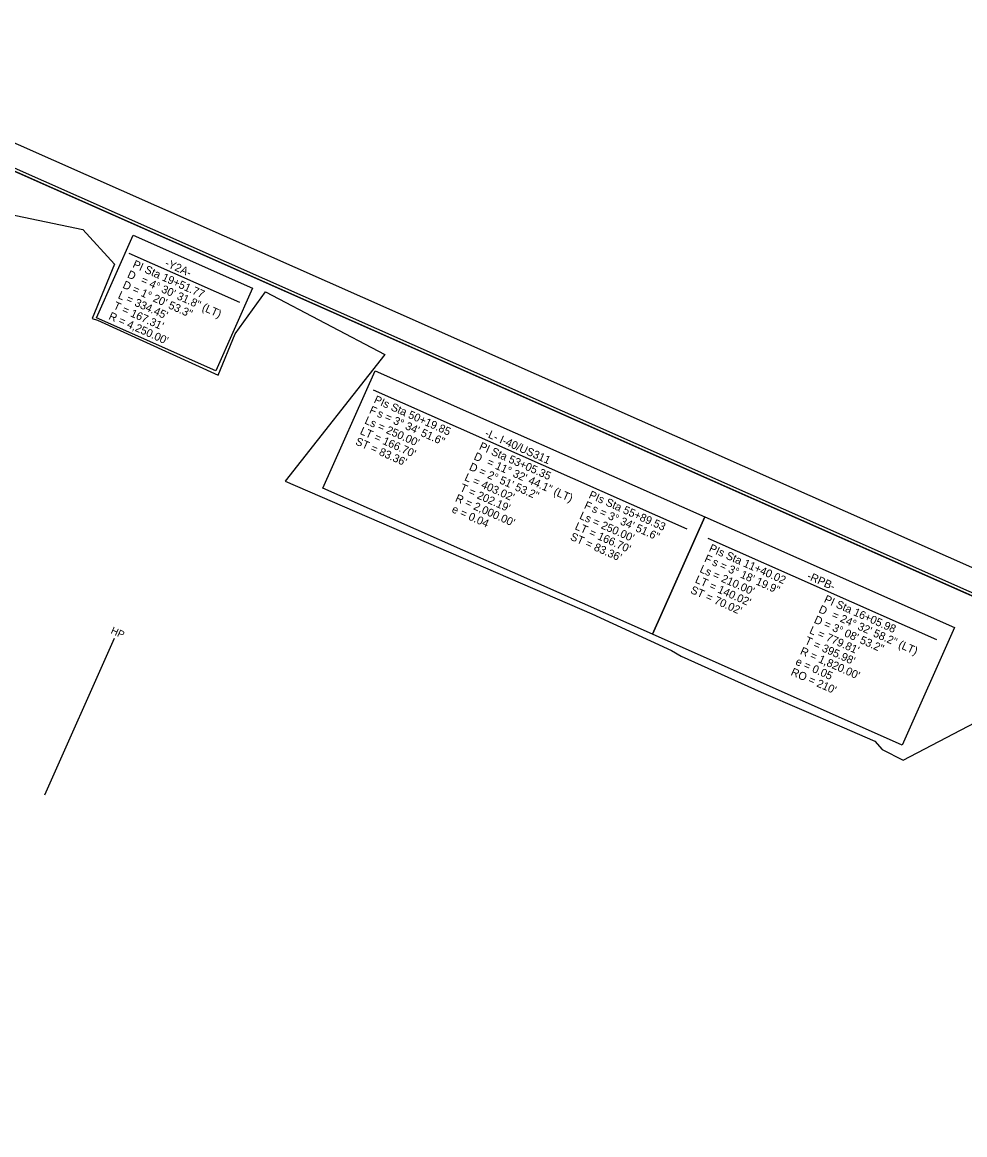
# Model space of a CAD drawing. Extents: x 1638962 to 2864602, y 841929 to 973236.
# Drawn here: x 1639652 to 1640476, y 842639 to 843612 of the extents above; entities that cross this region are included whole.
import ezdxf

# ---------------------------------------------------------------- set-up
doc = ezdxf.new("R2010")
doc.units = 0
for name, color, linetype in [('DEV STATIONARY SIGN DUAL MOUNT CELL', 7, 'Continuous'), ('Exist DTM Spot Elevation Cogo Number', 7, 'Continuous'), ('MARK RIGHT TURN ARROW CELL', 7, 'Continuous'), ('Prop EOT', 7, 'Continuous'), ('Prop Paved Shoulder', 7, 'Continuous'), ('Prop Roadway Bridge', 7, 'Continuous')]:
    doc.layers.add(name, color=color, linetype=linetype)

msp = doc.modelspace()

# ---------------------------------------------------------------- linework, layer by layer
at = {"layer": 'DEV STATIONARY SIGN DUAL MOUNT CELL'}
for points in [[(1640920.37, 842915.92), (1639549.09, 843523.96), (1639123.48, 842564.09), (1640494.73, 841956.06)], [(1639123.48, 842564.09), (1639549.06, 843523.95), (1640737.47, 842997.04), (1640676.66, 842859.85), (1640859.52, 842778.75), (1640494.73, 841956.06)]]:
    msp.add_lwpolyline(points, close=True, dxfattribs=at)
at = {"layer": 'Exist DTM Spot Elevation Cogo Number'}
for p, q in [((1639744.67, 843409.99), (1639841.47, 843367.07)), ((1639958.28, 843290.55), (1640232.57, 843168.93)), ((1640202.62, 843076.73), (1640248.19, 843179.5)), ((1640248.19, 843179.5), (1640466.57, 843082.67)), ((1640250.85, 843160.82), (1640450.94, 843072.1)), ((1640466.57, 843082.67), (1640420.99, 842979.9)), ((1640420.99, 842979.9), (1640202.62, 843076.73))]:
    msp.add_line(p, q, dxfattribs=at)
for points in [[(1639748.62, 843425.74), (1639853, 843379.46), (1639820.91, 843307.1), (1639716.54, 843353.38)], [(1639960.05, 843307.27), (1640248.19, 843179.5), (1640202.62, 843076.73), (1639914.48, 843204.49)]]:
    msp.add_lwpolyline(points, close=True, dxfattribs=at)
at = {"layer": 'MARK RIGHT TURN ARROW CELL'}
msp.add_line((1639671.4, 842936.31), (1639732.2, 843073.44), dxfattribs=at)
at = {"layer": 'Prop EOT'}
msp.add_lwpolyline([(1639169.19, 842543.82), (1640449.02, 841976.33), (1640788.91, 842742.87), (1640615.9, 842819.58), (1640701.62, 843012.92), (1639594.8, 843503.69)], close=True, dxfattribs=at)
msp.add_lwpolyline([(1639574.53, 843457.96), (1639704.62, 843430.63), (1639732.25, 843400.48), (1639712.8, 843352.82), (1639717.32, 843351.5), (1639822.84, 843303.26), (1639837.7, 843339.42), (1639864.3, 843376.29), (1639864.3, 843376.29), (1639968.61, 843321.42), (1639881.29, 843210.54), (1640149.46, 843094.59), (1640219.3, 843062.65), (1640227.76, 843057.7), (1640297.65, 843026.04), (1640368.11, 842995.95), (1640397.09, 842983.33), (1640403.3, 842975.95), (1640421.83, 842966.71), (1640484.57, 842999.74), (1640629.05, 842742.44), (1640617.73, 842617.59)], dxfattribs=at)
at = {"layer": 'Prop Paved Shoulder'}
msp.add_lwpolyline([(1638982.15, 842624.01), (1640505.14, 841948.72), (1640932.78, 842913.14), (1639409.79, 843588.45)], close=True, dxfattribs=at)
at = {"layer": 'Prop Roadway Bridge'}
msp.add_lwpolyline([(1638962.15, 842610.99), (1640501.15, 841928.59), (1640945, 842929.6), (1639406.01, 843612)], close=True, dxfattribs=at)
msp.add_lwpolyline([(1638962.15, 842610.99), (1640501.15, 841928.59), (1640945, 842929.6), (1639406.01, 843612)], close=True, dxfattribs=at)

# ---------------------------------------------------------------- texts
at = {"layer": 'Exist DTM Spot Elevation Cogo Number'}
for s, rotation, p in [('PI Sta 19+51.77', 335.96803, (1639747.48, 843397.93)), ('-Y2A-', 336.08714, (1639775.71, 843398.96)), ('D', 335.96803, (1639742.8, 843389.07)), ('D = 1%%d 20\' 53.3"', 335.96803, (1639738.72, 843379.94)), ('= 4%%d 30\' 31.8" (LT)', 335.96803, (1639754.65, 843384.11)), ("L = 334.45'", 335.96803, (1639734.65, 843370.81)), ("T = 167.31'", 335.96803, (1639730.58, 843361.67)), ("R = 4,250.00'", 335.96803, (1639726.51, 843352.54)), ('PIs Sta 50+19.85', 336.08714, (1639958.41, 843279.55)), ('F', 336.08714, (1639954.36, 843270.41)), ("Ls = 250.00'", 336.08714, (1639950.3, 843261.27)), ('s = 3%%d 34\' 51.6"', 336.08714, (1639961.23, 843267.36)), ("LT = 166.70'", 336.08714, (1639946.25, 843252.13)), ("ST = 83.36'", 336.08714, (1639942.2, 843242.99)), ('-L- I-40/US311', 336.08714, (1640055.43, 843250.21)), ('PI Sta 53+05.35', 336.08714, (1640050.41, 843238.76)), ('D = 2%%d 51\' 53.2"', 336.08714, (1640041.69, 843220.75)), ('D', 336.08714, (1640045.74, 843229.89)), ('= 11%%d 32\' 44.1" (LT)', 336.08714, (1640057.13, 843224.97)), ("L = 403.02'", 336.08714, (1640037.63, 843211.61)), ("T = 202.19'", 336.08714, (1640033.58, 843202.47)), ("R = 2,000.00'", 336.08714, (1640029.53, 843193.32)), ('PIs Sta 55+89.53', 336.08714, (1640146.26, 843196.26)), ('e = 0.04', 336.08714, (1640026.48, 843183.73)), ('F', 336.08714, (1640142.2, 843187.12)), ('s = 3%%d 34\' 51.6"', 336.08714, (1640149.07, 843184.07)), ("Ls = 250.00'", 336.08714, (1640138.15, 843177.98)), ("LT = 166.70'", 336.08714, (1640134.1, 843168.83)), ("ST = 83.36'", 336.08714, (1640130.04, 843159.69)), ('PIs Sta 11+40.02', 336.08714, (1640251.37, 843149.65)), ('F', 336.08714, (1640247.31, 843140.51)), ('s = 3%%d 18\' 19.9"', 336.08714, (1640254.18, 843137.47)), ("Ls = 210.00'", 336.08714, (1640243.26, 843131.37)), ('-RPB-', 336.08714, (1640337.06, 843125.33)), ("LT = 140.02'", 336.08714, (1640239.21, 843122.23)), ("ST = 70.02'", 336.08714, (1640235.15, 843113.09)), ('PI Sta 16+05.98', 336.08714, (1640351.92, 843105.06)), ('D', 336.08714, (1640347.26, 843096.2)), ('D = 3%%d 08\' 53.2"', 336.08714, (1640343.2, 843087.05)), ('= 24%%d 32\' 58.2" (LT)', 336.08714, (1640358.65, 843091.28)), ("L = 779.81'", 336.08714, (1640339.15, 843077.91)), ("T = 395.98'", 336.08714, (1640335.09, 843068.77)), ("R = 1,820.00'", 336.08714, (1640331.04, 843059.63)), ('e = 0.05', 336.08714, (1640326.99, 843050.49)), ("RO = 210'", 336.08714, (1640322.93, 843041.35))]:
    msp.add_text(s, height=7, rotation=rotation, dxfattribs=at).set_placement(p)
at = {"layer": 'MARK RIGHT TURN ARROW CELL'}
msp.add_text('HP', height=6.375, rotation=336.08714, dxfattribs=at).set_placement((1639728.38, 843077.76))

doc.saveas('drawing.dxf')
